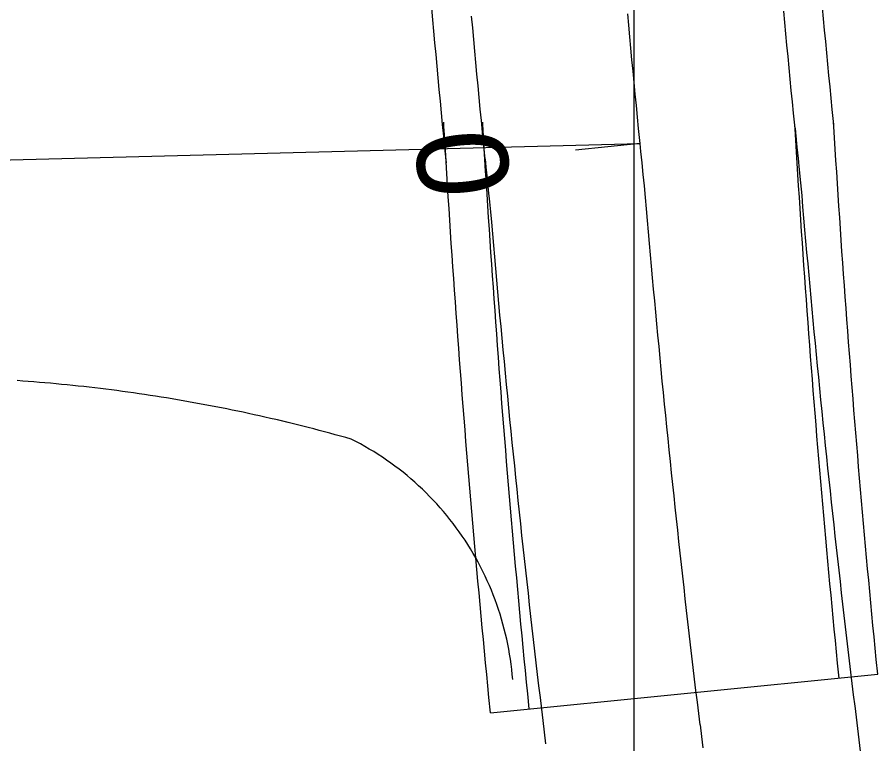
# Model space of a CAD drawing. Extents: x 2318076 to 2324211, y 613525 to 630327.
# Drawn here: x 2318832.9 to 2318899.2, y 614889.5 to 614945.5 of the extents above; entities that cross this region are included whole.
import ezdxf

# ---------------------------------------------------------------- set-up
doc = ezdxf.new("R2010")
doc.units = 0
for name, color, linetype in [('GE_P_CL_50', 7, 'Continuous'), ('GE_X_CL_50', 7, 'Continuous'), ('PV_P_EOP', 7, 'Continuous'), ('PV_P_Shoulder', 7, 'Continuous'), ('RS_Raster1', 7, 'Continuous'), ('SC_Scratch3', 7, 'Continuous')]:
    doc.layers.add(name, color=color, linetype=linetype)

msp = doc.modelspace()

# ---------------------------------------------------------------- linework, layer by layer
at = {"layer": 'GE_P_CL_50'}
msp.add_line((2318880.9, 614935.75), (2318875.925, 614935.256), dxfattribs=at)
msp.add_lwpolyline([(2318880.9, 614935.75), (2318880.785, 614936.91), (2318880.698, 614937.794), (2318880.612, 614938.679), (2318880.526, 614939.564), (2318880.441, 614940.449), (2318880.357, 614941.333), (2318880.274, 614942.218), (2318880.191, 614943.103), (2318880.109, 614943.988), (2318880.028, 614944.874), (2318879.947, 614945.759)], dxfattribs=at)
at = {"layer": 'GE_X_CL_50'}
for p, q in [((2318610.812, 614928.794), (2318880.9, 614935.75)), ((2318880.961, 614935.141), (2318880.9, 614935.75)), ((2318881.05, 614934.256), (2318880.961, 614935.141)), ((2318881.14, 614933.372), (2318881.05, 614934.256)), ((2318881.231, 614932.488), (2318881.14, 614933.372)), ((2318881.322, 614931.604), (2318881.231, 614932.488)), ((2318881.397, 614930.718), (2318881.322, 614931.604)), ((2318881.473, 614929.832), (2318881.397, 614930.718)), ((2318881.55, 614928.947), (2318881.473, 614929.832)), ((2318881.628, 614928.061), (2318881.55, 614928.947)), ((2318881.706, 614927.176), (2318881.628, 614928.061)), ((2318881.785, 614926.291), (2318881.706, 614927.176)), ((2318881.864, 614925.405), (2318881.785, 614926.291)), ((2318881.945, 614924.52), (2318881.864, 614925.405)), ((2318882.026, 614923.635), (2318881.945, 614924.52)), ((2318882.108, 614922.75), (2318882.026, 614923.635)), ((2318882.19, 614921.865), (2318882.108, 614922.75)), ((2318882.274, 614920.98), (2318882.19, 614921.865)), ((2318882.358, 614920.095), (2318882.274, 614920.98)), ((2318882.442, 614919.21), (2318882.358, 614920.095)), ((2318882.528, 614918.325), (2318882.442, 614919.21)), ((2318882.614, 614917.44), (2318882.528, 614918.325)), ((2318882.701, 614916.556), (2318882.614, 614917.44)), ((2318882.788, 614915.671), (2318882.701, 614916.556)), ((2318882.876, 614914.787), (2318882.788, 614915.671)), ((2318882.965, 614913.902), (2318882.876, 614914.787)), ((2318883.055, 614913.018), (2318882.965, 614913.902)), ((2318883.145, 614912.134), (2318883.055, 614913.018)), ((2318883.236, 614911.249), (2318883.145, 614912.134)), ((2318883.328, 614910.365), (2318883.236, 614911.249)), ((2318883.421, 614909.481), (2318883.328, 614910.365)), ((2318883.514, 614908.597), (2318883.421, 614909.481)), ((2318883.608, 614907.713), (2318883.514, 614908.597)), ((2318883.703, 614906.829), (2318883.608, 614907.713)), ((2318883.798, 614905.946), (2318883.703, 614906.829)), ((2318883.894, 614905.062), (2318883.798, 614905.946)), ((2318883.991, 614904.178), (2318883.894, 614905.062)), ((2318884.089, 614903.295), (2318883.991, 614904.178)), ((2318884.187, 614902.412), (2318884.089, 614903.295)), ((2318884.286, 614901.528), (2318884.187, 614902.412)), ((2318884.386, 614900.645), (2318884.286, 614901.528)), ((2318884.486, 614899.762), (2318884.386, 614900.645)), ((2318884.587, 614898.879), (2318884.486, 614899.762)), ((2318884.689, 614897.996), (2318884.587, 614898.879)), ((2318884.791, 614897.113), (2318884.689, 614897.996)), ((2318884.895, 614896.23), (2318884.791, 614897.113)), ((2318884.999, 614895.347), (2318884.895, 614896.23)), ((2318885.103, 614894.464), (2318884.999, 614895.347)), ((2318885.209, 614893.582), (2318885.103, 614894.464)), ((2318885.315, 614892.699), (2318885.209, 614893.582)), ((2318885.422, 614891.817), (2318885.315, 614892.699)), ((2318885.529, 614890.934), (2318885.422, 614891.817)), ((2318885.529, 614890.934), (2318885.637, 614890.052)), ((2318885.637, 614890.052), (2318885.746, 614889.17))]:
    msp.add_line(p, q, dxfattribs=at)
at = {"layer": 'PV_P_EOP'}
msp.add_line((2318869.368, 614891.87), (2318899.221, 614894.836), dxfattribs=at)
for points in [[(2318868.959, 614934.564), (2318868.843, 614935.729), (2318868.755, 614936.625), (2318868.668, 614937.519), (2318868.581, 614938.414), (2318868.496, 614939.308), (2318868.41, 614940.203), (2318868.326, 614941.097), (2318868.243, 614941.992), (2318868.16, 614942.887), (2318868.078, 614943.781), (2318867.996, 614944.676), (2318867.915, 614945.571)], [(2318892.841, 614936.936), (2318892.727, 614938.09), (2318892.641, 614938.964), (2318892.555, 614939.839), (2318892.471, 614940.714), (2318892.387, 614941.589), (2318892.304, 614942.464), (2318892.221, 614943.34), (2318892.139, 614944.215), (2318892.058, 614945.09), (2318891.978, 614945.966)], [(2318872.353, 614892.167), (2318872.237, 614893.332), (2318872.149, 614894.228), (2318872.062, 614895.122), (2318871.975, 614896.016), (2318871.89, 614896.911), (2318871.805, 614897.805), (2318871.72, 614898.7), (2318871.637, 614899.595), (2318871.554, 614900.489), (2318871.472, 614901.384), (2318871.39, 614902.279), (2318871.309, 614903.174), (2318871.23, 614904.069), (2318871.15, 614904.964), (2318871.072, 614905.859), (2318870.994, 614906.754), (2318870.917, 614907.65), (2318870.84, 614908.545), (2318870.765, 614909.44), (2318870.69, 614910.336), (2318870.616, 614911.231), (2318870.542, 614912.127), (2318870.469, 614913.022), (2318870.397, 614913.918), (2318870.326, 614914.814), (2318870.256, 614915.71), (2318870.186, 614916.606), (2318870.117, 614917.501), (2318870.048, 614918.397), (2318869.981, 614919.293), (2318869.914, 614920.19), (2318869.847, 614921.086), (2318869.782, 614921.982), (2318869.717, 614922.878), (2318869.653, 614923.774), (2318869.59, 614924.671), (2318869.527, 614925.567), (2318869.465, 614926.464), (2318869.404, 614927.36), (2318869.344, 614928.257), (2318869.284, 614929.153), (2318869.225, 614930.05), (2318869.167, 614930.947), (2318869.109, 614931.843), (2318869.052, 614932.74), (2318868.996, 614933.637), (2318868.941, 614934.534), (2318868.886, 614935.431), (2318868.832, 614936.328), (2318868.779, 614937.225), (2318868.769, 614937.404)], [(2318896.235, 614894.539), (2318896.121, 614895.693), (2318896.035, 614896.567), (2318895.95, 614897.442), (2318895.865, 614898.317), (2318895.781, 614899.192), (2318895.698, 614900.067), (2318895.615, 614900.943), (2318895.533, 614901.818), (2318895.452, 614902.693), (2318895.372, 614903.569), (2318895.292, 614904.444), (2318895.213, 614905.32), (2318895.135, 614906.196), (2318895.058, 614907.071), (2318894.981, 614907.947), (2318894.905, 614908.823), (2318894.829, 614909.699), (2318894.754, 614910.575), (2318894.68, 614911.451), (2318894.607, 614912.327), (2318894.535, 614913.203), (2318894.463, 614914.08), (2318894.391, 614914.956), (2318894.321, 614915.832), (2318894.251, 614916.709), (2318894.182, 614917.585), (2318894.114, 614918.462), (2318894.046, 614919.338), (2318893.979, 614920.215), (2318893.913, 614921.091), (2318893.848, 614921.968), (2318893.783, 614922.845), (2318893.719, 614923.722), (2318893.655, 614924.599), (2318893.593, 614925.476), (2318893.531, 614926.353), (2318893.469, 614927.23), (2318893.409, 614928.107), (2318893.349, 614928.984), (2318893.29, 614929.861), (2318893.231, 614930.738), (2318893.174, 614931.616), (2318893.117, 614932.493), (2318893.06, 614933.37), (2318893.005, 614934.248), (2318892.95, 614935.125), (2318892.896, 614936.003), (2318892.842, 614936.88), (2318892.811, 614937.404)], [(2318858.641, 614912.964), (2318858.228, 614913.081), (2318857.814, 614913.196), (2318857.401, 614913.31), (2318856.986, 614913.423), (2318856.572, 614913.534), (2318856.157, 614913.644), (2318855.741, 614913.752), (2318855.326, 614913.859), (2318852.941, 614914.465)], [(2318871.081, 614894.424), (2318871.047, 614894.818), (2318871.006, 614895.212), (2318870.959, 614895.605), (2318870.904, 614895.997), (2318870.843, 614896.388), (2318870.775, 614896.777), (2318870.7, 614897.166), (2318870.618, 614897.553), (2318870.53, 614897.939), (2318870.435, 614898.323), (2318870.333, 614898.706), (2318870.225, 614899.086), (2318870.11, 614899.465), (2318869.988, 614899.841), (2318869.86, 614900.216), (2318869.725, 614900.588), (2318869.584, 614900.958), (2318869.437, 614901.325), (2318869.283, 614901.689), (2318869.123, 614902.051), (2318868.957, 614902.41), (2318868.784, 614902.766), (2318868.605, 614903.119), (2318868.42, 614903.469), (2318868.229, 614903.815), (2318868.032, 614904.159), (2318867.829, 614904.498), (2318867.62, 614904.834), (2318867.405, 614905.166), (2318867.185, 614905.495), (2318866.959, 614905.82), (2318866.727, 614906.14), (2318866.49, 614906.457), (2318866.247, 614906.769), (2318865.999, 614907.077), (2318865.745, 614907.381), (2318865.487, 614907.68), (2318865.223, 614907.975), (2318864.954, 614908.265), (2318864.68, 614908.55), (2318864.401, 614908.83), (2318864.117, 614909.106), (2318863.828, 614909.377), (2318863.535, 614909.642), (2318863.238, 614909.902), (2318862.935, 614910.157), (2318862.629, 614910.407), (2318862.318, 614910.652), (2318862.002, 614910.89), (2318861.683, 614911.124), (2318861.36, 614911.352), (2318861.033, 614911.574), (2318860.702, 614911.79), (2318860.367, 614912), (2318860.028, 614912.205), (2318859.687, 614912.404), (2318859.341, 614912.597), (2318858.993, 614912.783), (2318858.641, 614912.964)]]:
    msp.add_lwpolyline(points, dxfattribs=at)
at = {"layer": 'PV_P_Shoulder'}
for points in [[(2318865.974, 614934.267), (2318865.858, 614935.434), (2318865.769, 614936.332), (2318865.682, 614937.229), (2318865.595, 614938.126), (2318865.509, 614939.023), (2318865.424, 614939.92), (2318865.339, 614940.817), (2318865.255, 614941.714), (2318865.172, 614942.611), (2318865.09, 614943.508), (2318865.008, 614944.406), (2318864.927, 614945.303), (2318864.847, 614946.2)], [(2318895.827, 614937.233), (2318895.712, 614938.385), (2318895.626, 614939.256), (2318895.541, 614940.129), (2318895.457, 614941.002), (2318895.373, 614941.874), (2318895.29, 614942.747), (2318895.208, 614943.62), (2318895.126, 614944.493), (2318895.046, 614945.366), (2318894.965, 614946.239)], [(2318869.368, 614891.87), (2318869.252, 614893.037), (2318869.163, 614893.935), (2318869.076, 614894.832), (2318868.989, 614895.729), (2318868.903, 614896.626), (2318868.818, 614897.523), (2318868.733, 614898.42), (2318868.65, 614899.317), (2318868.566, 614900.214), (2318868.484, 614901.111), (2318868.402, 614902.008), (2318868.322, 614902.906), (2318868.241, 614903.803), (2318868.162, 614904.701), (2318868.083, 614905.598), (2318868.005, 614906.496), (2318867.928, 614907.394), (2318867.851, 614908.291), (2318867.775, 614909.189), (2318867.7, 614910.087), (2318867.626, 614910.985), (2318867.552, 614911.883), (2318867.479, 614912.781), (2318867.407, 614913.679), (2318867.336, 614914.577), (2318867.265, 614915.475), (2318867.195, 614916.374), (2318867.125, 614917.272), (2318867.057, 614918.17), (2318866.989, 614919.069), (2318866.922, 614919.967), (2318866.855, 614920.866), (2318866.79, 614921.764), (2318866.725, 614922.663), (2318866.661, 614923.562), (2318866.597, 614924.461), (2318866.534, 614925.359), (2318866.472, 614926.258), (2318866.411, 614927.157), (2318866.35, 614928.056), (2318866.29, 614928.955), (2318866.231, 614929.854), (2318866.173, 614930.753), (2318866.115, 614931.652), (2318866.058, 614932.552), (2318866.002, 614933.451), (2318865.946, 614934.35), (2318865.892, 614935.25), (2318865.838, 614936.149), (2318865.784, 614937.048), (2318865.763, 614937.404)], [(2318899.221, 614894.836), (2318899.106, 614895.988), (2318899.021, 614896.859), (2318898.935, 614897.732), (2318898.851, 614898.604), (2318898.767, 614899.477), (2318898.684, 614900.35), (2318898.602, 614901.223), (2318898.521, 614902.096), (2318898.44, 614902.969), (2318898.36, 614903.842), (2318898.28, 614904.715), (2318898.201, 614905.588), (2318898.123, 614906.461), (2318898.046, 614907.335), (2318897.969, 614908.208), (2318897.893, 614909.082), (2318897.818, 614909.955), (2318897.744, 614910.829), (2318897.67, 614911.702), (2318897.597, 614912.576), (2318897.524, 614913.45), (2318897.453, 614914.324), (2318897.382, 614915.197), (2318897.311, 614916.071), (2318897.242, 614916.945), (2318897.173, 614917.819), (2318897.105, 614918.694), (2318897.037, 614919.568), (2318896.971, 614920.442), (2318896.905, 614921.316), (2318896.839, 614922.19), (2318896.775, 614923.065), (2318896.711, 614923.939), (2318896.648, 614924.814), (2318896.585, 614925.688), (2318896.523, 614926.563), (2318896.462, 614927.437), (2318896.402, 614928.312), (2318896.342, 614929.187), (2318896.283, 614930.062), (2318896.225, 614930.936), (2318896.167, 614931.811), (2318896.111, 614932.686), (2318896.054, 614933.561), (2318895.999, 614934.436), (2318895.944, 614935.311), (2318895.89, 614936.186), (2318895.837, 614937.062), (2318895.816, 614937.404)]]:
    msp.add_lwpolyline(points, dxfattribs=at)
at = {"layer": 'RS_Raster1'}
for p, q in [((2318892.841, 614936.944), (2318892.901, 614936.334)), ((2318868.96, 614934.556), (2318869.02, 614933.947))]:
    msp.add_line(p, q, dxfattribs=at)
for points in [[(2318892.9, 614936.344), (2318892.989, 614935.465), (2318893.078, 614934.59), (2318893.168, 614933.715), (2318893.269, 614932.729), (2318893.354, 614931.74), (2318893.429, 614930.864), (2318893.505, 614929.989), (2318893.581, 614929.113), (2318893.659, 614928.237), (2318893.737, 614927.361), (2318893.816, 614926.486), (2318893.895, 614925.61), (2318893.975, 614924.734), (2318894.056, 614923.859), (2318894.138, 614922.984), (2318894.22, 614922.108), (2318894.303, 614921.233), (2318894.387, 614920.358), (2318894.472, 614919.483), (2318894.557, 614918.608), (2318894.643, 614917.733), (2318894.729, 614916.858), (2318894.817, 614915.983), (2318894.905, 614915.108), (2318894.993, 614914.233), (2318895.083, 614913.359), (2318895.173, 614912.484), (2318895.264, 614911.61), (2318895.355, 614910.735), (2318895.447, 614909.861), (2318895.54, 614908.987), (2318895.634, 614908.113), (2318895.728, 614907.238), (2318895.823, 614906.364), (2318895.919, 614905.49), (2318896.016, 614904.617), (2318896.113, 614903.743), (2318896.211, 614902.869), (2318896.309, 614901.995), (2318896.409, 614901.122), (2318896.509, 614900.248), (2318896.609, 614899.375), (2318896.711, 614898.502), (2318896.813, 614897.629), (2318896.916, 614896.755), (2318897.019, 614895.882), (2318897.123, 614895.009), (2318897.228, 614894.136), (2318897.334, 614893.264), (2318897.441, 614892.386)], [(2318869.021, 614933.937), (2318869.111, 614933.048), (2318869.202, 614932.154), (2318869.293, 614931.26), (2318869.374, 614930.479), (2318869.441, 614929.696), (2318869.518, 614928.8), (2318869.595, 614927.905), (2318869.674, 614927.01), (2318869.753, 614926.115), (2318869.833, 614925.22), (2318869.913, 614924.325), (2318869.994, 614923.43), (2318870.076, 614922.535), (2318870.159, 614921.64), (2318870.243, 614920.746), (2318870.327, 614919.851), (2318870.412, 614918.956), (2318870.497, 614918.062), (2318870.584, 614917.167), (2318870.671, 614916.273), (2318870.758, 614915.379), (2318870.847, 614914.485), (2318870.936, 614913.59), (2318871.026, 614912.696), (2318871.117, 614911.802), (2318871.208, 614910.908), (2318871.3, 614910.015), (2318871.393, 614909.121), (2318871.487, 614908.227), (2318871.581, 614907.333), (2318871.676, 614906.44), (2318871.772, 614905.546), (2318871.868, 614904.653), (2318871.965, 614903.76), (2318872.063, 614902.866), (2318872.162, 614901.973), (2318872.261, 614901.08), (2318872.361, 614900.187), (2318872.462, 614899.294), (2318872.563, 614898.402), (2318872.666, 614897.509), (2318872.768, 614896.616), (2318872.872, 614895.724), (2318872.976, 614894.831), (2318873.082, 614893.939), (2318873.187, 614893.046), (2318873.294, 614892.154), (2318873.401, 614891.262), (2318873.509, 614890.37), (2318873.617, 614889.483)], [(2318858.641, 614912.964), (2318858.228, 614913.081), (2318857.814, 614913.196), (2318857.401, 614913.31), (2318856.986, 614913.423), (2318856.572, 614913.534), (2318856.157, 614913.644), (2318855.741, 614913.752), (2318855.326, 614913.859), (2318854.91, 614913.965), (2318854.493, 614914.069), (2318854.076, 614914.172), (2318853.659, 614914.273), (2318853.241, 614914.373), (2318852.824, 614914.472), (2318852.405, 614914.569), (2318851.987, 614914.664), (2318851.568, 614914.759), (2318851.149, 614914.851), (2318850.729, 614914.943), (2318850.309, 614915.033), (2318849.889, 614915.121), (2318849.469, 614915.208), (2318849.048, 614915.294), (2318848.627, 614915.378), (2318848.205, 614915.461), (2318847.784, 614915.542), (2318847.362, 614915.622), (2318846.94, 614915.7), (2318846.517, 614915.777), (2318846.095, 614915.853), (2318845.672, 614915.927), (2318845.248, 614915.999), (2318844.825, 614916.071), (2318844.401, 614916.14), (2318843.977, 614916.209), (2318843.553, 614916.275), (2318843.129, 614916.341), (2318842.704, 614916.405), (2318842.279, 614916.467), (2318841.854, 614916.528), (2318841.429, 614916.588), (2318841.004, 614916.646), (2318840.578, 614916.703), (2318840.152, 614916.758), (2318839.726, 614916.812), (2318839.3, 614916.864), (2318838.874, 614916.915), (2318838.448, 614916.964), (2318838.021, 614917.012), (2318837.594, 614917.059), (2318837.167, 614917.104), (2318836.74, 614917.147), (2318836.313, 614917.189), (2318835.886, 614917.23), (2318835.458, 614917.269), (2318835.03, 614917.307), (2318834.603, 614917.343), (2318834.175, 614917.378), (2318833.747, 614917.411), (2318833.319, 614917.443), (2318832.891, 614917.474)], [(2318871.081, 614894.424), (2318871.047, 614894.818), (2318871.006, 614895.212), (2318870.959, 614895.605), (2318870.904, 614895.997), (2318870.843, 614896.388), (2318870.775, 614896.777), (2318870.7, 614897.166), (2318870.618, 614897.553), (2318870.53, 614897.939), (2318870.435, 614898.323), (2318870.333, 614898.706), (2318870.225, 614899.086), (2318870.11, 614899.465), (2318869.988, 614899.841), (2318869.86, 614900.216), (2318869.725, 614900.588), (2318869.584, 614900.958), (2318869.437, 614901.325), (2318869.283, 614901.689), (2318869.123, 614902.051), (2318868.957, 614902.41), (2318868.784, 614902.766), (2318868.605, 614903.119), (2318868.42, 614903.469), (2318868.229, 614903.815), (2318868.032, 614904.159), (2318867.829, 614904.498), (2318867.62, 614904.834), (2318867.405, 614905.166), (2318867.185, 614905.495), (2318866.959, 614905.82), (2318866.727, 614906.14), (2318866.49, 614906.457), (2318866.247, 614906.769), (2318865.999, 614907.077), (2318865.745, 614907.381), (2318865.487, 614907.68), (2318865.223, 614907.975), (2318864.954, 614908.265), (2318864.68, 614908.55), (2318864.401, 614908.83), (2318864.117, 614909.106), (2318863.828, 614909.377), (2318863.535, 614909.642), (2318863.238, 614909.902), (2318862.935, 614910.157), (2318862.629, 614910.407), (2318862.318, 614910.652), (2318862.002, 614910.89), (2318861.683, 614911.124), (2318861.36, 614911.352), (2318861.033, 614911.574), (2318860.702, 614911.79), (2318860.367, 614912), (2318860.028, 614912.205), (2318859.687, 614912.404), (2318859.341, 614912.597), (2318858.993, 614912.783), (2318858.641, 614912.964)], [(2318897.44, 614892.396), (2318897.548, 614891.518), (2318897.655, 614890.646), (2318897.764, 614889.773), (2318897.873, 614888.901)]]:
    msp.add_lwpolyline(points, dxfattribs=at)
at = {"layer": 'SC_Scratch3'}
msp.add_line((2318880.454, 614778.412), (2318880.454, 630327.224), dxfattribs=at)

# ---------------------------------------------------------------- texts
at = {"layer": 'GE_P_CL_50'}
msp.add_text('0', height=7, rotation=95.67353, dxfattribs=at).set_placement((2318870.971, 614931.97))

doc.saveas('drawing.dxf')
